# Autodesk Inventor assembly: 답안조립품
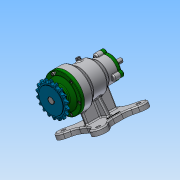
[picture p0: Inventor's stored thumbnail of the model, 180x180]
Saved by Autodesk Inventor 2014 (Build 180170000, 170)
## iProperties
Created: 2017-03
Part Number: 답안조립품
Document SubType Name: Assembly
Designer: NET
Author: NET
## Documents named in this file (14)
- C:\Users\NET\Desktop\470307V1022\답안조립품.iam
- C:\Users\NET\Desktop\470307V1022\본체.ipt
- C:\Users\NET\Desktop\470307V1022\축.ipt
- C:\Users\NET\Desktop\470307V1022\베어링-6203.ipt
- C:\Users\NET\Desktop\470307V1022\베어링-6200.ipt
- C:\Users\NET\Desktop\470307V1022\뒤커버.ipt
- C:\Users\NET\Desktop\470307V1022\볼트 M4 x 12.ipt
- C:\Users\NET\Desktop\470307V1022\오일 실 10 20 7.ipt
- C:\Users\NET\Desktop\470307V1022\앞커버.ipt
- C:\Users\NET\Desktop\470307V1022\오일 실 17 30 8.ipt
- C:\Users\NET\Desktop\470307V1022\스프로킷.ipt
- C:\Users\NET\Desktop\470307V1022\키5x5.ipt
- C:\Users\NET\Desktop\470307V1022\볼트 M5 x 10.ipt
- 볼트 M5 x 10.ipt
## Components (9 placed, 1 different names)
1. ISO 4762 M4 x 12:1
2. ISO 4762 M4 x 12:2
3. ISO 4762 M4 x 12:3
4. ISO 4762 M4 x 12:4
5. ISO 4762 M4 x 12:5
6. ISO 4762 M4 x 12:6
7. ISO 4762 M4 x 12:7
8. ISO 4762 M4 x 12:8
9. ISO 4762 M4 x 12:9
